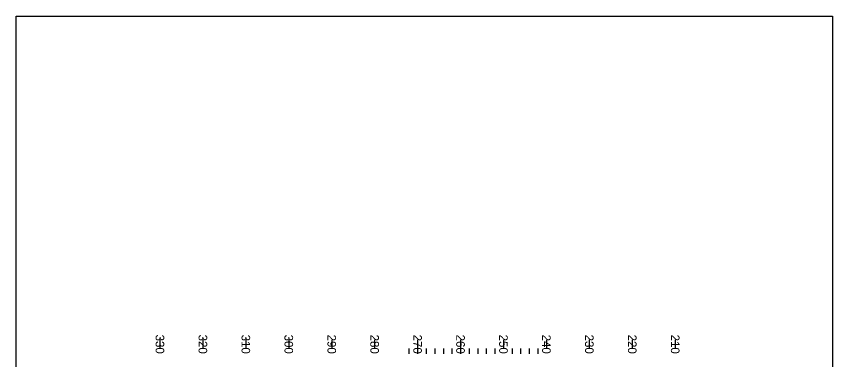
# Model space of a CAD drawing. Extents: x 1313293 to 1314187, y 2087928 to 2089557.
# Drawn here: x 1313400.2 to 1313590.3, y 2088951.7 to 2089031.5 of the extents above; entities that cross this region are included whole.
import ezdxf

# ---------------------------------------------------------------- set-up
doc = ezdxf.new("R2010")
doc.units = 0
doc.layers.add('B-Gen-Construction Line', color=7, linetype='Continuous')
doc.layers.add('B-Gen-Hidden', color=7, linetype='Continuous')

msp = doc.modelspace()

# ---------------------------------------------------------------- linework, layer by layer
at = {"layer": 'B-Gen-Construction Line'}
for p, q in [((1313433.66, 2088956.28), (1313433.66, 2088954.28)), ((1313443.66, 2088956.28), (1313443.66, 2088954.28)), ((1313453.66, 2088956.28), (1313453.66, 2088954.28)), ((1313463.66, 2088956.28), (1313463.66, 2088954.28)), ((1313473.66, 2088956.28), (1313473.66, 2088954.28)), ((1313483.66, 2088956.28), (1313483.66, 2088954.28)), ((1313493.66, 2088956.28), (1313493.66, 2088954.28)), ((1313503.66, 2088956.28), (1313503.66, 2088954.28)), ((1313513.66, 2088956.28), (1313513.66, 2088954.28)), ((1313523.66, 2088956.28), (1313523.66, 2088954.28)), ((1313533.66, 2088956.28), (1313533.66, 2088954.28)), ((1313543.66, 2088956.28), (1313543.66, 2088954.28)), ((1313553.66, 2088956.28), (1313553.66, 2088954.28)), ((1313491.66, 2088954.28), (1313491.66, 2088953.02)), ((1313493.66, 2088954.28), (1313493.66, 2088953.02)), ((1313495.66, 2088954.28), (1313495.66, 2088953.02)), ((1313497.66, 2088954.28), (1313497.66, 2088953.02)), ((1313499.66, 2088954.28), (1313499.66, 2088953.02)), ((1313501.66, 2088954.28), (1313501.66, 2088953.02)), ((1313503.66, 2088954.28), (1313503.66, 2088953.02)), ((1313505.66, 2088954.28), (1313505.66, 2088953.02)), ((1313507.66, 2088954.28), (1313507.66, 2088953.02)), ((1313509.66, 2088954.28), (1313509.66, 2088953.02)), ((1313511.66, 2088954.28), (1313511.66, 2088953.02)), ((1313515.66, 2088954.28), (1313515.66, 2088953.02)), ((1313517.66, 2088954.28), (1313517.66, 2088953.02)), ((1313519.66, 2088954.28), (1313519.66, 2088953.02)), ((1313521.66, 2088954.28), (1313521.66, 2088953.02))]:
    msp.add_line(p, q, dxfattribs=at)
at = {"layer": 'B-Gen-Hidden'}
msp.add_lwpolyline([(1313400.21, 2088564.79), (1313400.21, 2089031.55), (1313590.33, 2089031.55), (1313590.33, 2088564.79)], close=True, dxfattribs=at)

# ---------------------------------------------------------------- texts
at = {"layer": 'B-Gen-Construction Line'}
for s, p in [('330', (1313432.66, 2088957.48)), ('330', (1313432.66, 2088957.48)), ('320', (1313442.66, 2088957.48)), ('310', (1313452.66, 2088957.48)), ('300', (1313462.66, 2088957.48)), ('290', (1313472.66, 2088957.48)), ('280', (1313482.66, 2088957.48)), ('270', (1313492.66, 2088957.48)), ('260', (1313502.66, 2088957.48)), ('250', (1313512.66, 2088957.48)), ('240', (1313522.66, 2088957.48)), ('230', (1313532.66, 2088957.48)), ('220', (1313542.66, 2088957.48)), ('210', (1313552.66, 2088957.48))]:
    msp.add_text(s, height=2, rotation=270, dxfattribs=at).set_placement(p)

doc.saveas('drawing.dxf')
